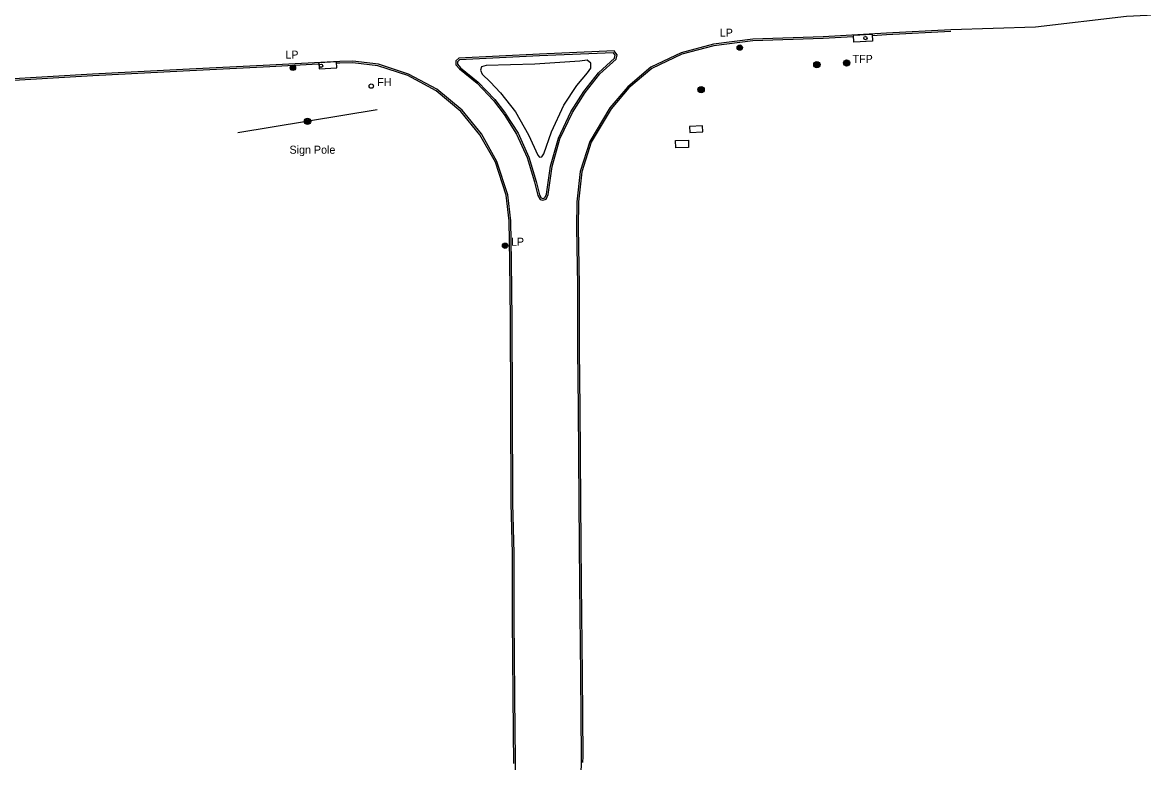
# Model space of a CAD drawing. Extents: x 2402803 to 2427059, y 6985292 to 6997652.
# Drawn here: x 2416364 to 2417036, y 6990360 to 6990803 of the extents above; entities that cross this region are included whole.
import ezdxf

# ---------------------------------------------------------------- set-up
doc = ezdxf.new("R2010")
doc.units = 0
for name, color, linetype in [('p_dtm sidewalk', 7, 'Continuous'), ('p_road - paved curb', 7, 'Continuous'), ('p_road bridge end', 7, 'Continuous'), ('p_structure general', 7, 'Continuous'), ('p_structure sign', 7, 'Continuous'), ('p_structure slab', 7, 'Continuous'), ('p_utility manhole', 7, 'Continuous')]:
    doc.layers.add(name, color=color, linetype=linetype)

msp = doc.modelspace()

# ---------------------------------------------------------------- linework, layer by layer
at = {"layer": 'p_dtm sidewalk'}
for points in [[(2416688.86, 6990753.65), (2416696.52, 6990765.5), (2416702.99, 6990773.11), (2416704.92, 6990775.92), (2416704.93, 6990778.79), (2416702.7, 6990780.53), (2416698.33, 6990780.09), (2416671.44, 6990778.32), (2416642.24, 6990777.5), (2416639.35, 6990776.72), (2416638.72, 6990774.56), (2416639.71, 6990772.17), (2416644.59, 6990767.69), (2416650.81, 6990761.13), (2416659.83, 6990749.7)], [(2416659.83, 6990749.7), (2416667.63, 6990735.89), (2416673.19, 6990723.77), (2416674.18, 6990722.55), (2416675.6, 6990722.67), (2416676.83, 6990724.45), (2416681.28, 6990737.75), (2416688.86, 6990753.65)]]:
    msp.add_lwpolyline(points, dxfattribs=at)
at = {"layer": 'p_road - paved curb'}
for points in [[(2417059.26, 6990808.45), (2417026.27, 6990806.74), (2416971.75, 6990800.45), (2416920.81, 6990798.82)], [(2416920.81, 6990798.82), (2416882.27, 6990796.77), (2416844.22, 6990794.66), (2416802.05, 6990793.14), (2416778.62, 6990790.24), (2416759.12, 6990785.06), (2416740.91, 6990776.5), (2416727.07, 6990764.66), (2416716.38, 6990752.06), (2416704.3, 6990731.86), (2416698.64, 6990713.93), (2416696.61, 6990695.74), (2416696.27, 6990680.28), (2416696.86, 6990645.67), (2416696.98, 6990607.04), (2416697.27, 6990572.04), (2416697.72, 6990515.69)], [(2416862.26, 6990794.66), (2416844.27, 6990793.66), (2416802.13, 6990792.14), (2416778.81, 6990789.26), (2416759.46, 6990784.12), (2416741.46, 6990775.65), (2416727.78, 6990763.95), (2416717.2, 6990751.48), (2416705.22, 6990731.45), (2416699.62, 6990713.72), (2416697.61, 6990695.67), (2416697.27, 6990680.28), (2416697.86, 6990645.68), (2416697.98, 6990607.05), (2416698.27, 6990572.05), (2416698.72, 6990515.7)], [(2416920.86, 6990797.82), (2416882.32, 6990795.77), (2416873.84, 6990795.3)], [(2416693.88, 6990749.19), (2416701.56, 6990761.3), (2416710.37, 6990772.39), (2416720.15, 6990781.22), (2416720.71, 6990783.85), (2416718.94, 6990786.12), (2416674.21, 6990784.18), (2416625.88, 6990781.76), (2416623.92, 6990780.14), (2416623.9, 6990777.88), (2416626.09, 6990775.36), (2416636.72, 6990766.76), (2416646.54, 6990756.35), (2416652.98, 6990747.96)], [(2416693.04, 6990749.73), (2416700.74, 6990761.88), (2416709.64, 6990773.08), (2416719.24, 6990781.75), (2416719.63, 6990783.6), (2416718.47, 6990785.1), (2416674.26, 6990783.18), (2416626.26, 6990780.78), (2416624.92, 6990779.67), (2416624.9, 6990778.25), (2416626.79, 6990776.08), (2416637.4, 6990767.5), (2416647.3, 6990757), (2416653.77, 6990748.57)], [(2416541.4, 6990778.18), (2416512.38, 6990776.61), (2416460.35, 6990774.06), (2416406.2, 6990771.23), (2416352.07, 6990768.13), (2416299.5, 6990765.92), (2416258.22, 6990763.81), (2416238.49, 6990762.81)], [(2416658.16, 6990514.82), (2416657.97, 6990574.14), (2416657.71, 6990625.16), (2416657.29, 6990659.87), (2416657.03, 6990684.39), (2416655.11, 6990699.86), (2416648.67, 6990719.83), (2416639.31, 6990736.44), (2416627.73, 6990750.66), (2416612.66, 6990763.15), (2416595.66, 6990772.26), (2416577.51, 6990778.24), (2416562.2, 6990779.94), (2416554.38, 6990779.88), (2416512.33, 6990777.61), (2416460.3, 6990775.06), (2416406.15, 6990772.23), (2416352.02, 6990769.13)], [(2416657.16, 6990514.82), (2416656.97, 6990574.14), (2416656.71, 6990625.15), (2416656.29, 6990659.86), (2416656.03, 6990684.32), (2416654.13, 6990699.64), (2416647.75, 6990719.43), (2416638.48, 6990735.87), (2416627.02, 6990749.95), (2416612.1, 6990762.32), (2416595.26, 6990771.34), (2416577.3, 6990777.26), (2416562.15, 6990778.94), (2416554.41, 6990778.88), (2416552.71, 6990778.79)], [(2416652.98, 6990747.96), (2416660.47, 6990736.35), (2416666.86, 6990722.21), (2416671.23, 6990707.61), (2416673.2, 6990699.45), (2416674.51, 6990697.14), (2416676.26, 6990696.75), (2416678.07, 6990697.32), (2416679.34, 6990700), (2416681.75, 6990716.84), (2416686.44, 6990733.43), (2416693.88, 6990749.19)], [(2416653.82, 6990748.5), (2416661.35, 6990736.83), (2416667.8, 6990722.56), (2416672.2, 6990707.87), (2416674.14, 6990699.82), (2416675.16, 6990698.02), (2416676.22, 6990697.78), (2416677.35, 6990698.14), (2416678.37, 6990700.29), (2416680.77, 6990717.05), (2416685.5, 6990733.78), (2416692.98, 6990749.62)], [(2416629.95, 6990076.35), (2416640.54, 6990107.56), (2416648.11, 6990135.45), (2416654.63, 6990170.59), (2416658.3, 6990201.91), (2416660.15, 6990229.26), (2416660.12, 6990274.09), (2416660.23, 6990331.5), (2416659.5, 6990377.99), (2416659.5, 6990377.99), (2416659.06, 6990445.62), (2416659.04, 6990485.15), (2416658.16, 6990514.82)], [(2416658.8, 6990359.03), (2416658.5, 6990377.99), (2416658.5, 6990377.99), (2416658.06, 6990445.62), (2416658.04, 6990485.13), (2416657.16, 6990514.79)], [(2416697.72, 6990515.69), (2416698.18, 6990466.61), (2416698.76, 6990412.26), (2416699.07, 6990363.27), (2416698.72, 6990335.82), (2416701.24, 6990329.2), (2416704.56, 6990322.94), (2416710.52, 6990317.23), (2416716.75, 6990312.75), (2416725.28, 6990309.81), (2416747.12, 6990309.6), (2416763.46, 6990309.31), (2416788.29, 6990309.47), (2416818.8, 6990308.89), (2416844.51, 6990306.43), (2416877.31, 6990301.27), (2416908.47, 6990294.83), (2416942.19, 6990285.52), (2416978.14, 6990272.21), (2417010.39, 6990258.51), (2417030.46, 6990248.61)], [(2416698.72, 6990515.7), (2416699.18, 6990466.62), (2416699.76, 6990412.27), (2416700.07, 6990363.27), (2416700.02, 6990359.7)]]:
    msp.add_lwpolyline(points, dxfattribs=at)
at = {"layer": 'p_road bridge end'}
for points in [[(2416862.48, 6990795.57), (2416873.68, 6990796.18), (2416873.9, 6990792.06), (2416862.7, 6990791.45)], [(2416552.46, 6990779.68), (2416541.8, 6990779.1), (2416542, 6990775.46), (2416552.66, 6990776.04)]]:
    msp.add_lwpolyline(points, close=True, dxfattribs=at)
at = {"layer": 'p_structure general'}
for centre in [(2416869.6, 6990793.9), (2416543.12, 6990777.31)]:
    msp.add_circle(centre, 1, dxfattribs=at)
at = {"layer": 'p_structure sign'}
msp.add_line((2416576.83, 6990750.77), (2416493.23, 6990737.09), dxfattribs=at)
for radius in [1.9, 1.44, 0.973, 0.539, 0.192]:
    msp.add_circle((2416535.03, 6990743.93), radius, dxfattribs=at)
at = {"layer": 'p_structure slab'}
for points in [[(2416764.34, 6990737.26), (2416772.04, 6990737.69), (2416771.83, 6990741.35), (2416764.13, 6990740.92)], [(2416755.79, 6990732.38), (2416763.47, 6990732.65), (2416763.62, 6990728.36), (2416755.94, 6990728.09)]]:
    msp.add_lwpolyline(points, close=True, dxfattribs=at)
at = {"layer": 'p_utility manhole'}
for centre, radius in [((2416794.25, 6990788.17), 1.6), ((2416794.25, 6990788.17), 1.3), ((2416794.25, 6990788.17), 1), ((2416794.25, 6990788.17), 0.539), ((2416794.25, 6990788.17), 0.192), ((2416858.36, 6990778.97), 1.9), ((2416858.36, 6990778.97), 1.44), ((2416526.26, 6990776.01), 1.6), ((2416526.26, 6990776.01), 1.3), ((2416526.26, 6990776.01), 1), ((2416526.26, 6990776.01), 0.539), ((2416526.26, 6990776.01), 0.192), ((2416840.54, 6990777.93), 1.9), ((2416840.54, 6990777.93), 1.44), ((2416840.54, 6990777.93), 0.973), ((2416840.54, 6990777.93), 0.539), ((2416840.54, 6990777.93), 0.192), ((2416858.36, 6990778.97), 0.973), ((2416858.36, 6990778.97), 0.539), ((2416858.36, 6990778.97), 0.192), ((2416573.3, 6990765.05), 1.3), ((2416771.11, 6990762.9), 1.9), ((2416771.11, 6990762.9), 1.44), ((2416771.11, 6990762.9), 0.973), ((2416771.11, 6990762.9), 0.539), ((2416771.11, 6990762.9), 0.192), ((2416653.5, 6990669.39), 1.6), ((2416653.5, 6990669.39), 1.3), ((2416653.5, 6990669.39), 1), ((2416653.5, 6990669.39), 0.539), ((2416653.5, 6990669.39), 0.192)]:
    msp.add_circle(centre, radius, dxfattribs=at)

# ---------------------------------------------------------------- texts
at = {"layer": 'p_structure sign'}
msp.add_text('Sign Pole', height=4.8, dxfattribs=at).set_placement((2416524.25, 6990724.53))
at = {"layer": 'p_utility manhole'}
for s, p in [('  LP', (2416778.72, 6990794.71)), ('  LP', (2416518.19, 6990781.54)), ('  TFP', (2416858.36, 6990778.97)), ('  FH', (2416573.29, 6990765.04)), ('  LP', (2416653.5, 6990669.39))]:
    msp.add_text(s, height=4.8, dxfattribs=at).set_placement(p)

doc.saveas('drawing.dxf')
